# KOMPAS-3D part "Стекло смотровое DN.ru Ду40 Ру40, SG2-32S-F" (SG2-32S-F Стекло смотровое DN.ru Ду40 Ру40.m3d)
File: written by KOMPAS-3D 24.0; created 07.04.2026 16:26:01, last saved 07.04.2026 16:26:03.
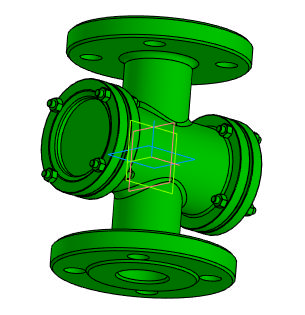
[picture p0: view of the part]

Document properties: Автор: Main; Полное имя файла: D:\DN.ru Аутсерс\Стекло смотровое DN.ru\SG2-32S-F Стекло смотровое DN.ru Ду40 Ру40\SG2-32S-F Стекло смотровое DN.ru Ду40 Ру40.m3d

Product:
- Body: Тело 1  | qty 1
    Масса: 7.458074
- Part/product: Стекло смотровое DN.ru Ду40 Ру40  | designation SG2-32S-F
    Масса: 9
    Раздел спецификации: Прочие изделия
    Примечание: D500-00107

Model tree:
1. Операция без истории:1

Expressions: SG2-32S-F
